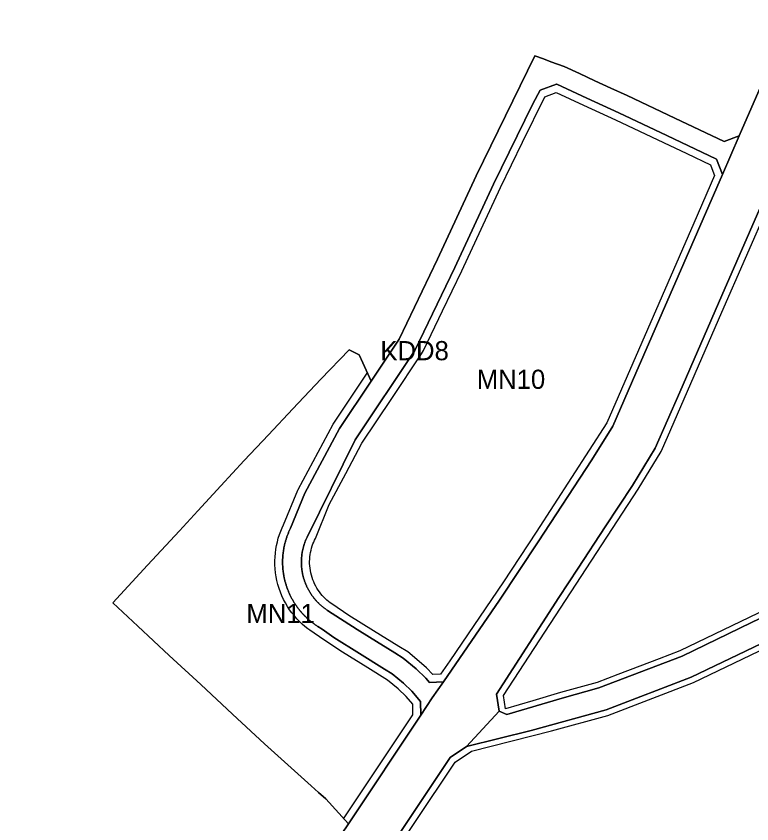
# Model space of a CAD drawing. Extents: x 7439486 to 7443435, y 5551288 to 5554556.
# Drawn here: x 7440979.6 to 7441363, y 5553147.6 to 5553568.6 of the extents above; entities that cross this region are included whole.
import ezdxf

# ---------------------------------------------------------------- set-up
doc = ezdxf.new("R2010")
doc.units = 0
for name, color, linetype in [('linie_rozgraniczajace', 7, 'Continuous'), ('linie_zabudowy_nieprzekraczalne', 7, 'Continuous'), ('oznaczenia_przeznaczen', 7, 'Continuous')]:
    doc.layers.add(name, color=color, linetype=linetype)

msp = doc.modelspace()

# ---------------------------------------------------------------- linework, layer by layer
at = {"layer": 'linie_rozgraniczajace'}
for points in [[(7441383.69, 5553568.6), (7441356.47, 5553506.19), (7441348.63, 5553503.26), (7441322.9, 5553515.43), (7441297.99, 5553527.2), (7441289.6, 5553531.09), (7441281.22, 5553534.97), (7441273.2, 5553538.65), (7441265.19, 5553542.32), (7441258.35, 5553544.85), (7441254.49, 5553546.27), (7441250, 5553547.93), (7441219.32, 5553485.35), (7441199.19, 5553441.87), (7441179.26, 5553400.3), (7441164.55, 5553378.28), (7441160.2, 5553387.91), (7441158.35, 5553392.03), (7441153.12, 5553394.76), (7441138.45, 5553379.31), (7441123.77, 5553363.86), (7441111.06, 5553350.4), (7441098.34, 5553336.94), (7441086.32, 5553323.84), (7441074.3, 5553310.74), (7441064.77, 5553300.37), (7441048.06, 5553282.37), (7441029.94, 5553262.84), (7441043.01, 5553250.65), (7441059.38, 5553235.42), (7441075.75, 5553220.2), (7441092.37, 5553204.78), (7441108.99, 5553189.36), (7441121.19, 5553178.4), (7441133.39, 5553167.44), (7441137.19, 5553164.03), (7441140.99, 5553160.62), (7441152.78, 5553147.71), (7441142.61, 5553132.46)], [(7441142.61, 5553132.46), (7441152.78, 5553147.71), (7441190.43, 5553204.2), (7441196.45, 5553213.24), (7441202.26, 5553221.66), (7441231.56, 5553264.21), (7441251.62, 5553294.69), (7441279.72, 5553337.4), (7441290.52, 5553354.96), (7441302.57, 5553382.6), (7441324.58, 5553433.06), (7441347.68, 5553486.02), (7441356.47, 5553506.19), (7441383.69, 5553568.6)], [(7441118.48, 5553282.46), (7441118.46, 5553282.86), (7441118.45, 5553283.26), (7441118.45, 5553283.66), (7441118.45, 5553284.05), (7441118.45, 5553284.45), (7441118.45, 5553284.85), (7441118.47, 5553285.25), (7441118.48, 5553285.65), (7441118.5, 5553286.05), (7441118.52, 5553286.45), (7441118.55, 5553286.84), (7441118.58, 5553287.24), (7441118.61, 5553287.64), (7441118.65, 5553288.04), (7441118.69, 5553288.43), (7441118.74, 5553288.83), (7441118.79, 5553289.23), (7441118.84, 5553289.62), (7441118.9, 5553290.02), (7441118.96, 5553290.41), (7441119.03, 5553290.8), (7441119.1, 5553291.2), (7441119.17, 5553291.59), (7441119.25, 5553291.98), (7441119.33, 5553292.37), (7441119.42, 5553292.76), (7441119.5, 5553293.15), (7441119.6, 5553293.54), (7441119.7, 5553293.92), (7441119.8, 5553294.31), (7441119.9, 5553294.69), (7441120.01, 5553295.08), (7441120.12, 5553295.46), (7441120.24, 5553295.84), (7441120.36, 5553296.22), (7441120.48, 5553296.6), (7441120.61, 5553296.98), (7441120.74, 5553297.36), (7441120.88, 5553297.73), (7441121.02, 5553298.1), (7441121.16, 5553298.48), (7441121.31, 5553298.85), (7441121.46, 5553299.22), (7441121.61, 5553299.59), (7441121.77, 5553299.95), (7441121.93, 5553300.32), (7441122.1, 5553300.68), (7441122.26, 5553301.04), (7441122.44, 5553301.4), (7441122.6, 5553301.73), (7441130.07, 5553320), (7441148.17, 5553353.76), (7441164.55, 5553378.28), (7441179.26, 5553400.3), (7441199.19, 5553441.87), (7441219.32, 5553485.35), (7441250, 5553547.93), (7441254.49, 5553546.27), (7441258.35, 5553544.85), (7441265.19, 5553542.32), (7441273.2, 5553538.65), (7441281.22, 5553534.97), (7441289.6, 5553531.09), (7441297.99, 5553527.2), (7441322.9, 5553515.43), (7441348.63, 5553503.26), (7441356.47, 5553506.19), (7441347.68, 5553486.02), (7441344.66, 5553494.08), (7441318.65, 5553506.38), (7441293.75, 5553518.15), (7441285.39, 5553522.02), (7441277.03, 5553525.89), (7441269.2, 5553529.48), (7441261.37, 5553533.07), (7441261.27, 5553533.11), (7441252.78, 5553529.99), (7441248.88, 5553522.94), (7441228.34, 5553481.05), (7441208.24, 5553437.61), (7441187.45, 5553394.25), (7441156.36, 5553347.71), (7441131.36, 5553297.38), (7441131.33, 5553297.3), (7441131.18, 5553296.99), (7441131.03, 5553296.68), (7441130.89, 5553296.36), (7441130.75, 5553296.05), (7441130.61, 5553295.73), (7441130.47, 5553295.41), (7441130.35, 5553295.09), (7441130.22, 5553294.76), (7441130.1, 5553294.44), (7441129.98, 5553294.12), (7441129.86, 5553293.79), (7441129.75, 5553293.46), (7441129.65, 5553293.13), (7441129.54, 5553292.8), (7441129.44, 5553292.47)], [(7441128.26, 5553282.89), (7441128.25, 5553283.23), (7441128.24, 5553283.58), (7441128.23, 5553283.92), (7441128.24, 5553284.27), (7441128.24, 5553284.62), (7441128.25, 5553284.96), (7441128.26, 5553285.31), (7441128.28, 5553285.66), (7441128.3, 5553286), (7441128.32, 5553286.35), (7441128.35, 5553286.69), (7441128.39, 5553287.04), (7441128.42, 5553287.38), (7441128.46, 5553287.72), (7441128.51, 5553288.07), (7441128.56, 5553288.41), (7441128.61, 5553288.75), (7441128.66, 5553289.1), (7441128.72, 5553289.44), (7441128.79, 5553289.78), (7441128.86, 5553290.12), (7441128.93, 5553290.46), (7441129.01, 5553290.79), (7441129.09, 5553291.13), (7441129.17, 5553291.47), (7441129.26, 5553291.8), (7441129.35, 5553292.14), (7441129.44, 5553292.47), (7441129.54, 5553292.8), (7441129.65, 5553293.13), (7441129.75, 5553293.46), (7441129.86, 5553293.79), (7441129.98, 5553294.12), (7441130.1, 5553294.44), (7441130.22, 5553294.76), (7441130.35, 5553295.09), (7441130.47, 5553295.41), (7441130.61, 5553295.73), (7441130.75, 5553296.05), (7441130.89, 5553296.36), (7441131.03, 5553296.68), (7441131.18, 5553296.99), (7441131.33, 5553297.3), (7441131.36, 5553297.38), (7441156.36, 5553347.71), (7441187.45, 5553394.25), (7441208.24, 5553437.61), (7441228.34, 5553481.05), (7441248.88, 5553522.94), (7441252.78, 5553529.99), (7441261.27, 5553533.11), (7441261.37, 5553533.07), (7441269.2, 5553529.48), (7441277.03, 5553525.89), (7441285.39, 5553522.02), (7441293.75, 5553518.15), (7441318.65, 5553506.38), (7441344.66, 5553494.08), (7441347.68, 5553486.02), (7441324.58, 5553433.06), (7441302.57, 5553382.6), (7441290.52, 5553354.96), (7441279.72, 5553337.4), (7441251.62, 5553294.69), (7441231.56, 5553264.21), (7441202.26, 5553221.66), (7441195.01, 5553221.37), (7441193.16, 5553223.59), (7441188.06, 5553228.43), (7441181.37, 5553233.96), (7441176.91, 5553236.73), (7441163.77, 5553244.9), (7441157.27, 5553248.93), (7441141.94, 5553258.85), (7441141.65, 5553259.03), (7441141.36, 5553259.23), (7441141.08, 5553259.42), (7441140.8, 5553259.62), (7441140.52, 5553259.83), (7441140.24, 5553260.03), (7441139.96, 5553260.24), (7441139.69, 5553260.46), (7441139.42, 5553260.67), (7441139.15, 5553260.89), (7441138.88, 5553261.11), (7441138.62, 5553261.34), (7441138.36, 5553261.57), (7441138.1, 5553261.8), (7441137.84, 5553262.03), (7441137.59, 5553262.27), (7441137.34, 5553262.51), (7441137.09, 5553262.75), (7441136.85, 5553262.99), (7441136.61, 5553263.24), (7441136.37, 5553263.49), (7441136.13, 5553263.75), (7441135.9, 5553264), (7441135.67, 5553264.26), (7441135.45, 5553264.53)], [(7441369.63, 5553473.83), (7441347.49, 5553423.07), (7441336.49, 5553397.84), (7441325.48, 5553372.61), (7441319.11, 5553357.99), (7441312.73, 5553343.37), (7441306.77, 5553333.67), (7441300.82, 5553323.98), (7441286.66, 5553302.46), (7441272.5, 5553280.95), (7441262.4, 5553265.6), (7441229.96, 5553215.27), (7441231.29, 5553206.35), (7441214.23, 5553188.01), (7441205.81, 5553182.2), (7441190.17, 5553158.74), (7441163.18, 5553118.25)], [(7441420.83, 5553280.36), (7441362.94, 5553252.51), (7441326.71, 5553235.07), (7441283.31, 5553218.43), (7441264.17, 5553213.2), (7441235.3, 5553204.64), (7441231.29, 5553206.35), (7441229.96, 5553215.27), (7441262.4, 5553265.6), (7441272.5, 5553280.95), (7441286.66, 5553302.46), (7441300.82, 5553323.98), (7441306.77, 5553333.67), (7441312.73, 5553343.37), (7441319.11, 5553357.99), (7441325.48, 5553372.61), (7441336.49, 5553397.84), (7441347.49, 5553423.07), (7441369.63, 5553473.83)], [(7441029.94, 5553262.84), (7441048.06, 5553282.37), (7441064.77, 5553300.37), (7441074.3, 5553310.74), (7441086.32, 5553323.84), (7441098.34, 5553336.94), (7441111.06, 5553350.4), (7441123.77, 5553363.86), (7441138.45, 5553379.31), (7441153.12, 5553394.76), (7441158.35, 5553392.03), (7441160.2, 5553387.91), (7441164.55, 5553378.28), (7441148.17, 5553353.76), (7441130.07, 5553320), (7441122.6, 5553301.73), (7441122.44, 5553301.4), (7441122.26, 5553301.04), (7441122.1, 5553300.68), (7441121.93, 5553300.32), (7441121.77, 5553299.95), (7441121.61, 5553299.59), (7441121.46, 5553299.22), (7441121.31, 5553298.85), (7441121.16, 5553298.48), (7441121.02, 5553298.1), (7441120.88, 5553297.73), (7441120.74, 5553297.36), (7441120.61, 5553296.98), (7441120.48, 5553296.6), (7441120.36, 5553296.22), (7441120.24, 5553295.84), (7441120.12, 5553295.46), (7441120.01, 5553295.08), (7441119.9, 5553294.69), (7441119.8, 5553294.31), (7441119.7, 5553293.92), (7441119.6, 5553293.54), (7441119.5, 5553293.15), (7441119.42, 5553292.76), (7441119.33, 5553292.37), (7441119.25, 5553291.98), (7441119.17, 5553291.59), (7441119.1, 5553291.2), (7441119.03, 5553290.8), (7441118.96, 5553290.41), (7441118.9, 5553290.02), (7441118.84, 5553289.62), (7441118.79, 5553289.23), (7441118.74, 5553288.83), (7441118.69, 5553288.43), (7441118.65, 5553288.04), (7441118.61, 5553287.64), (7441118.58, 5553287.24), (7441118.55, 5553286.84), (7441118.52, 5553286.45), (7441118.5, 5553286.05), (7441118.48, 5553285.65), (7441118.47, 5553285.25), (7441118.45, 5553284.85), (7441118.45, 5553284.45), (7441118.45, 5553284.05), (7441118.45, 5553283.66), (7441118.45, 5553283.26), (7441118.46, 5553282.86), (7441118.48, 5553282.46), (7441118.5, 5553282.06), (7441118.52, 5553281.66), (7441118.54, 5553281.26), (7441118.57, 5553280.87), (7441118.61, 5553280.47), (7441118.64, 5553280.07), (7441118.69, 5553279.68), (7441118.73, 5553279.28), (7441118.78, 5553278.88), (7441118.84, 5553278.49), (7441118.89, 5553278.09), (7441118.95, 5553277.7), (7441119.02, 5553277.31), (7441119.09, 5553276.91), (7441119.16, 5553276.52), (7441119.24, 5553276.13), (7441119.32, 5553275.74), (7441119.41, 5553275.35), (7441119.5, 5553274.96), (7441119.59, 5553274.57), (7441119.69, 5553274.19), (7441119.79, 5553273.8), (7441119.89, 5553273.41), (7441120, 5553273.03), (7441120.11, 5553272.65), (7441120.23, 5553272.27), (7441120.35, 5553271.89), (7441120.47, 5553271.51), (7441120.6, 5553271.13), (7441120.73, 5553270.75), (7441120.86, 5553270.38), (7441121, 5553270), (7441121.15, 5553269.63), (7441121.29, 5553269.26)], [(7441129.44, 5553292.47), (7441129.35, 5553292.14), (7441129.26, 5553291.8), (7441129.17, 5553291.47), (7441129.09, 5553291.13), (7441129.01, 5553290.79), (7441128.93, 5553290.46), (7441128.86, 5553290.12), (7441128.79, 5553289.78), (7441128.72, 5553289.44), (7441128.66, 5553289.1), (7441128.61, 5553288.75), (7441128.56, 5553288.41), (7441128.51, 5553288.07), (7441128.46, 5553287.72), (7441128.42, 5553287.38), (7441128.39, 5553287.04), (7441128.35, 5553286.69), (7441128.32, 5553286.35), (7441128.3, 5553286), (7441128.28, 5553285.66), (7441128.26, 5553285.31), (7441128.25, 5553284.96), (7441128.24, 5553284.62), (7441128.24, 5553284.27), (7441128.23, 5553283.92), (7441128.24, 5553283.58), (7441128.25, 5553283.23), (7441128.26, 5553282.89), (7441128.27, 5553282.54), (7441128.29, 5553282.19), (7441128.31, 5553281.85), (7441128.34, 5553281.5), (7441128.37, 5553281.16), (7441128.41, 5553280.81), (7441128.45, 5553280.47), (7441128.49, 5553280.12), (7441128.54, 5553279.78), (7441128.59, 5553279.44), (7441128.64, 5553279.1), (7441128.7, 5553278.76), (7441128.77, 5553278.41), (7441128.83, 5553278.07), (7441128.9, 5553277.74), (7441128.98, 5553277.4), (7441129.06, 5553277.06), (7441129.14, 5553276.72), (7441129.22, 5553276.39), (7441129.32, 5553276.05), (7441129.41, 5553275.72), (7441129.51, 5553275.39), (7441129.61, 5553275.06), (7441129.71, 5553274.73), (7441129.82, 5553274.4), (7441129.94, 5553274.07), (7441130.05, 5553273.75), (7441130.17, 5553273.42), (7441130.3, 5553273.1), (7441130.43, 5553272.78), (7441130.56, 5553272.45), (7441130.7, 5553272.14), (7441130.83, 5553271.82), (7441130.98, 5553271.5), (7441131.12, 5553271.19), (7441131.27, 5553270.88), (7441131.43, 5553270.57), (7441131.59, 5553270.26), (7441131.75, 5553269.95), (7441131.91, 5553269.65), (7441132.08, 5553269.34), (7441132.25, 5553269.04), (7441132.42, 5553268.74), (7441132.6, 5553268.45), (7441132.78, 5553268.15), (7441132.97, 5553267.86), (7441133.16, 5553267.57), (7441133.35, 5553267.28), (7441133.54, 5553266.99), (7441133.74, 5553266.71), (7441133.94, 5553266.43), (7441134.15, 5553266.15), (7441134.36, 5553265.87), (7441134.57, 5553265.6), (7441134.78, 5553265.33), (7441135, 5553265.06), (7441135.22, 5553264.79), (7441135.45, 5553264.53), (7441135.67, 5553264.26), (7441135.9, 5553264), (7441136.13, 5553263.75), (7441136.37, 5553263.49), (7441136.61, 5553263.24), (7441136.85, 5553262.99), (7441137.09, 5553262.75), (7441137.34, 5553262.51), (7441137.59, 5553262.27), (7441137.84, 5553262.03), (7441138.1, 5553261.8), (7441138.36, 5553261.57), (7441138.62, 5553261.34)], [(7441120.47, 5553271.51), (7441120.35, 5553271.89), (7441120.23, 5553272.27), (7441120.11, 5553272.65), (7441120, 5553273.03), (7441119.89, 5553273.41), (7441119.79, 5553273.8), (7441119.69, 5553274.19), (7441119.59, 5553274.57), (7441119.5, 5553274.96), (7441119.41, 5553275.35), (7441119.32, 5553275.74), (7441119.24, 5553276.13), (7441119.16, 5553276.52), (7441119.09, 5553276.91), (7441119.02, 5553277.31), (7441118.95, 5553277.7), (7441118.89, 5553278.09), (7441118.84, 5553278.49), (7441118.78, 5553278.88), (7441118.73, 5553279.28), (7441118.69, 5553279.68), (7441118.64, 5553280.07), (7441118.61, 5553280.47), (7441118.57, 5553280.87), (7441118.54, 5553281.26), (7441118.52, 5553281.66), (7441118.5, 5553282.06), (7441118.48, 5553282.46)], [(7441135.45, 5553264.53), (7441135.22, 5553264.79), (7441135, 5553265.06), (7441134.78, 5553265.33), (7441134.57, 5553265.6), (7441134.36, 5553265.87), (7441134.15, 5553266.15), (7441133.94, 5553266.43), (7441133.74, 5553266.71), (7441133.54, 5553266.99), (7441133.35, 5553267.28), (7441133.16, 5553267.57), (7441132.97, 5553267.86), (7441132.78, 5553268.15), (7441132.6, 5553268.45), (7441132.42, 5553268.74), (7441132.25, 5553269.04), (7441132.08, 5553269.34), (7441131.91, 5553269.65), (7441131.75, 5553269.95), (7441131.59, 5553270.26), (7441131.43, 5553270.57), (7441131.27, 5553270.88), (7441131.12, 5553271.19), (7441130.98, 5553271.5), (7441130.83, 5553271.82), (7441130.7, 5553272.14), (7441130.56, 5553272.45), (7441130.43, 5553272.78), (7441130.3, 5553273.1), (7441130.17, 5553273.42), (7441130.05, 5553273.75), (7441129.94, 5553274.07), (7441129.82, 5553274.4), (7441129.71, 5553274.73), (7441129.61, 5553275.06), (7441129.51, 5553275.39), (7441129.41, 5553275.72), (7441129.32, 5553276.05), (7441129.22, 5553276.39), (7441129.14, 5553276.72), (7441129.06, 5553277.06), (7441128.98, 5553277.4), (7441128.9, 5553277.74), (7441128.83, 5553278.07), (7441128.77, 5553278.41), (7441128.7, 5553278.76), (7441128.64, 5553279.1), (7441128.59, 5553279.44), (7441128.54, 5553279.78), (7441128.49, 5553280.12), (7441128.45, 5553280.47), (7441128.41, 5553280.81), (7441128.37, 5553281.16), (7441128.34, 5553281.5), (7441128.31, 5553281.85), (7441128.29, 5553282.19), (7441128.27, 5553282.54), (7441128.26, 5553282.89)], [(7441368.14, 5553241.69), (7441331.46, 5553224.04), (7441287.05, 5553207.02), (7441248.05, 5553196.36), (7441214.23, 5553188.01), (7441231.29, 5553206.35), (7441235.3, 5553204.64), (7441264.17, 5553213.2), (7441283.31, 5553218.43), (7441326.71, 5553235.07), (7441362.94, 5553252.51), (7441420.83, 5553280.36)], [(7441138.62, 5553261.34), (7441138.88, 5553261.11), (7441139.15, 5553260.89), (7441139.42, 5553260.67), (7441139.69, 5553260.46), (7441139.96, 5553260.24), (7441140.24, 5553260.03), (7441140.52, 5553259.83), (7441140.8, 5553259.62), (7441141.08, 5553259.42), (7441141.36, 5553259.23), (7441141.65, 5553259.03), (7441141.94, 5553258.85), (7441157.27, 5553248.93), (7441163.77, 5553244.9), (7441176.91, 5553236.73), (7441181.37, 5553233.96), (7441188.06, 5553228.43), (7441193.16, 5553223.59), (7441195.01, 5553221.37), (7441202.26, 5553221.66), (7441196.45, 5553213.24), (7441190.43, 5553204.2), (7441190.25, 5553211.45), (7441185.85, 5553216.74), (7441181.42, 5553220.94), (7441175.52, 5553225.83), (7441171.64, 5553228.24), (7441158.49, 5553236.4), (7441145.19, 5553244.66), (7441139.07, 5553249.1), (7441136.81, 5553250.51), (7441136.47, 5553250.73), (7441136.14, 5553250.95), (7441135.81, 5553251.17), (7441135.48, 5553251.4), (7441135.15, 5553251.63), (7441134.83, 5553251.86), (7441134.51, 5553252.09), (7441134.19, 5553252.33), (7441133.87, 5553252.58), (7441133.56, 5553252.82), (7441133.25, 5553253.07), (7441132.94, 5553253.32), (7441132.63, 5553253.58), (7441132.33, 5553253.84), (7441132.03, 5553254.1), (7441131.73, 5553254.36), (7441131.43, 5553254.63), (7441131.14, 5553254.9), (7441130.85, 5553255.17), (7441130.56, 5553255.45), (7441130.27, 5553255.73), (7441129.99, 5553256.01), (7441129.71, 5553256.29), (7441129.44, 5553256.58), (7441129.16, 5553256.87), (7441128.89, 5553257.16), (7441128.62, 5553257.46), (7441128.36, 5553257.76), (7441128.1, 5553258.06), (7441127.84, 5553258.36), (7441127.58, 5553258.67), (7441127.33, 5553258.98), (7441127.08, 5553259.29), (7441126.83, 5553259.6), (7441126.59, 5553259.92), (7441126.35, 5553260.24), (7441126.11, 5553260.56), (7441125.88, 5553260.88), (7441125.65, 5553261.21), (7441125.42, 5553261.53), (7441125.2, 5553261.86), (7441124.98, 5553262.2), (7441124.76, 5553262.53), (7441124.54, 5553262.87), (7441124.33, 5553263.21), (7441124.13, 5553263.55), (7441123.92, 5553263.89), (7441123.72, 5553264.24), (7441123.53, 5553264.58), (7441123.33, 5553264.93), (7441123.14, 5553265.28), (7441122.96, 5553265.64), (7441122.77, 5553265.99), (7441122.6, 5553266.35), (7441122.42, 5553266.7), (7441122.25, 5553267.06), (7441122.08, 5553267.43), (7441121.91, 5553267.79), (7441121.75, 5553268.15), (7441121.6, 5553268.52), (7441121.44, 5553268.89), (7441121.29, 5553269.26), (7441121.15, 5553269.63), (7441121, 5553270), (7441120.86, 5553270.38), (7441120.73, 5553270.75), (7441120.6, 5553271.13), (7441120.47, 5553271.51)], [(7441121.29, 5553269.26), (7441121.44, 5553268.89), (7441121.6, 5553268.52), (7441121.75, 5553268.15), (7441121.91, 5553267.79), (7441122.08, 5553267.43), (7441122.25, 5553267.06), (7441122.42, 5553266.7), (7441122.6, 5553266.35), (7441122.77, 5553265.99), (7441122.96, 5553265.64), (7441123.14, 5553265.28), (7441123.33, 5553264.93), (7441123.53, 5553264.58), (7441123.72, 5553264.24), (7441123.92, 5553263.89), (7441124.13, 5553263.55), (7441124.33, 5553263.21), (7441124.54, 5553262.87), (7441124.76, 5553262.53), (7441124.98, 5553262.2), (7441125.2, 5553261.86), (7441125.42, 5553261.53), (7441125.65, 5553261.21), (7441125.88, 5553260.88), (7441126.11, 5553260.56), (7441126.35, 5553260.24), (7441126.59, 5553259.92), (7441126.83, 5553259.6), (7441127.08, 5553259.29), (7441127.33, 5553258.98), (7441127.58, 5553258.67), (7441127.84, 5553258.36), (7441128.1, 5553258.06), (7441128.36, 5553257.76), (7441128.62, 5553257.46), (7441128.89, 5553257.16), (7441129.16, 5553256.87), (7441129.44, 5553256.58), (7441129.71, 5553256.29), (7441129.99, 5553256.01), (7441130.27, 5553255.73), (7441130.56, 5553255.45), (7441130.85, 5553255.17), (7441131.14, 5553254.9), (7441131.43, 5553254.63), (7441131.73, 5553254.36), (7441132.03, 5553254.1), (7441132.33, 5553253.84), (7441132.63, 5553253.58), (7441132.94, 5553253.32), (7441133.25, 5553253.07), (7441133.56, 5553252.82), (7441133.87, 5553252.58), (7441134.19, 5553252.33), (7441134.51, 5553252.09), (7441134.83, 5553251.86), (7441135.15, 5553251.63), (7441135.48, 5553251.4), (7441135.81, 5553251.17), (7441136.14, 5553250.95), (7441136.47, 5553250.73), (7441136.81, 5553250.51), (7441139.07, 5553249.1), (7441145.19, 5553244.66), (7441158.49, 5553236.4), (7441171.64, 5553228.24), (7441175.52, 5553225.83), (7441181.42, 5553220.94), (7441185.85, 5553216.74), (7441190.25, 5553211.45), (7441190.43, 5553204.2), (7441152.78, 5553147.71), (7441140.99, 5553160.62), (7441137.19, 5553164.03), (7441133.39, 5553167.44), (7441121.19, 5553178.4), (7441108.99, 5553189.36), (7441092.37, 5553204.78), (7441075.75, 5553220.2), (7441059.38, 5553235.42), (7441043.01, 5553250.65), (7441029.94, 5553262.84)], [(7441004.21, 5552885.58), (7441021.96, 5552914.19), (7441032.79, 5552930.21), (7441037.68, 5552937.27), (7441042.56, 5552944.33), (7441046.31, 5552951.11), (7441050.05, 5552957.88), (7441054.89, 5552966.78), (7441059.73, 5552975.68), (7441074.06, 5552994.68), (7441088.38, 5553013.69), (7441095.08, 5553023.14), (7441125.78, 5553065.97), (7441163.18, 5553118.25), (7441190.17, 5553158.74), (7441205.81, 5553182.2), (7441214.23, 5553188.01), (7441248.05, 5553196.36), (7441287.05, 5553207.02), (7441331.46, 5553224.04), (7441368.14, 5553241.69)]]:
    msp.add_lwpolyline(points, dxfattribs=at)
at = {"layer": 'linie_zabudowy_nieprzekraczalne'}
for points in [[(7441200.72, 5553225.6), (7441196.82, 5553225.44), (7441193.4, 5553228.88), (7441187.21, 5553234.32), (7441183.71, 5553237.22), (7441179.03, 5553240.13), (7441165.88, 5553248.29), (7441153, 5553256.29), (7441144.14, 5553262.27), (7441143.26, 5553262.89), (7441142.39, 5553263.56), (7441141.53, 5553264.28), (7441140.7, 5553265.04), (7441139.89, 5553265.85), (7441139.11, 5553266.7), (7441138.35, 5553267.59), (7441137.63, 5553268.53), (7441136.95, 5553269.5), (7441136.31, 5553270.51), (7441135.71, 5553271.56), (7441135.16, 5553272.64), (7441134.66, 5553273.75), (7441134.2, 5553274.88), (7441133.8, 5553276.04), (7441133.46, 5553277.21), (7441133.16, 5553278.4), (7441132.93, 5553279.6), (7441132.75, 5553280.81), (7441132.62, 5553282.02), (7441132.55, 5553283.23), (7441132.54, 5553284.43), (7441132.58, 5553285.63), (7441132.68, 5553286.81), (7441132.83, 5553287.98), (7441133.02, 5553289.13), (7441133.27, 5553290.26), (7441133.56, 5553291.37), (7441133.9, 5553292.45), (7441134.27, 5553293.5), (7441134.69, 5553294.52), (7441135.14, 5553295.5), (7441135.56, 5553296.43), (7441142.75, 5553314.02), (7441151.46, 5553330.26), (7441159.81, 5553345.98), (7441175.36, 5553369.25), (7441190.9, 5553392.53), (7441191.88, 5553394.25), (7441201.87, 5553415.08), (7441211.85, 5553435.91), (7441221.9, 5553457.62), (7441231.95, 5553479.33), (7441243.54, 5553502.96), (7441255.13, 5553526.6), (7441261.11, 5553528.79), (7441275.36, 5553522.26), (7441283.71, 5553518.39), (7441292.06, 5553514.52), (7441304.49, 5553508.65), (7441316.92, 5553502.77), (7441329.2, 5553496.96), (7441341.48, 5553491.16), (7441342.71, 5553487.89), (7441343.61, 5553485.46), (7441332.78, 5553460.62), (7441287.41, 5553356.59), (7441250.7, 5553299.67), (7441233.66, 5553273.77), (7441205.57, 5553232.64), (7441200.72, 5553225.6)], [(7441376.11, 5553262.17), (7441361.64, 5553255.21), (7441343.52, 5553246.49), (7441334.52, 5553242.16), (7441325.52, 5553237.83), (7441314.72, 5553233.69), (7441304.72, 5553229.86), (7441293.15, 5553225.42), (7441282.37, 5553221.29), (7441272.95, 5553218.71), (7441263.35, 5553216.09), (7441248.88, 5553211.8), (7441234.64, 5553207.58), (7441233.62, 5553214.48), (7441303.77, 5553322.1), (7441315.84, 5553341.74), (7441319.08, 5553349.16), (7441347.47, 5553414.25), (7441372.01, 5553470.53)], [(7441150.24, 5553150.21), (7441186.42, 5553204.5), (7441186.29, 5553209.97), (7441182.93, 5553214), (7441178.77, 5553217.95), (7441173.18, 5553222.57), (7441162.96, 5553228.92), (7441149.67, 5553237.17), (7441139.9, 5553243.56), (7441132.63, 5553248.52), (7441131.58, 5553249.29), (7441130.1, 5553250.48), (7441128.65, 5553251.75), (7441127.24, 5553253.09), (7441125.88, 5553254.52), (7441124.57, 5553256.02), (7441123.31, 5553257.59), (7441122.12, 5553259.24), (7441121, 5553260.95), (7441119.96, 5553262.73), (7441118.99, 5553264.56), (7441118.11, 5553266.44), (7441117.32, 5553268.37), (7441116.61, 5553270.35), (7441116, 5553272.35), (7441115.49, 5553274.38), (7441115.08, 5553276.44), (7441114.77, 5553278.5), (7441114.55, 5553280.57), (7441114.43, 5553282.64), (7441114.42, 5553284.7), (7441114.49, 5553286.74), (7441114.67, 5553288.77), (7441114.93, 5553290.76), (7441115.28, 5553292.73), (7441115.71, 5553294.65), (7441116.22, 5553296.53), (7441116.81, 5553298.36), (7441117.47, 5553300.14), (7441118.2, 5553301.86), (7441118.98, 5553303.53), (7441126.37, 5553321.51), (7441126.55, 5553321.89), (7441144.84, 5553355.98), (7441162.61, 5553382.58)], [(7440979.56, 5552840.3), (7441030.3, 5552920.28), (7441047.45, 5552945.95), (7441062.68, 5552973.78), (7441073.35, 5552987.94), (7441113.27, 5553042.52), (7441166.06, 5553116.27), (7441208.35, 5553179.7), (7441216.85, 5553185.57), (7441258.57, 5553196.13), (7441287.98, 5553204.16), (7441332.65, 5553221.29), (7441383.71, 5553245.85)]]:
    msp.add_lwpolyline(points, dxfattribs=at)

# ---------------------------------------------------------------- texts
at = {"layer": 'oznaczenia_przeznaczen'}
for s, p in [('KDD8', (7441169.42, 5553389.25)), ('MN10', (7441219.67, 5553374.33)), ('MN11', (7441099.57, 5553252.26))]:
    msp.add_text(s, height=10, dxfattribs=at).set_placement(p)

doc.saveas('drawing.dxf')
